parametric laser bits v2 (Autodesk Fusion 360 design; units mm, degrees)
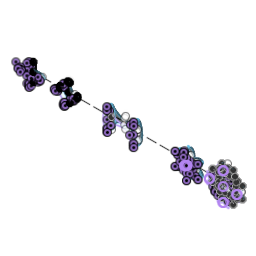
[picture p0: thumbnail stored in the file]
parameter "length" = 101.6
parameter "ch" = 6.35
parameter "width" = 25.4
parameter "sl" = 19.05
sketch "Sketch1" plane through (0, 0, 0) normal (0, 1, 0) x axis (1, 0, 0)
  line L1 (609.6, 0) -> (0, 0)
  line L2 (101.6, 50.8) -> (101.6, -50.8)
  line L3 (114.3, 50.8) -> (114.3, -50.8)
  line L4 (88.9, -50.8) -> (88.9, 50.8)
  line L5 (101.6, 50.8) -> (101.6, -50.8)
  line L6 (103.5558, -63.5) -> (99.6442, -63.5)
  line L7 (103.5558, -44.45) -> (103.5558, -63.5)
  line L8 (99.6442, -44.45) -> (103.5558, -44.45)
  line L9 (99.6442, -63.5) -> (99.6442, -44.45)
  line L10 (101.6, -44.45) -> (101.6, -63.5)
  line L11 (103.5558, 44.45) -> (103.5558, 63.5)
  line L12 (99.6442, 44.45) -> (103.5558, 44.45)
  line L13 (99.6442, 63.5) -> (99.6442, 44.45)
  line L14 (103.5558, 63.5) -> (99.6442, 63.5)
  line L15 (152.4, -12.7) -> (50.8, -12.7)
  line L16 (50.8, 12.7) -> (152.4, 12.7)
  line L17 (38.1, -0.762) -> (57.15, -0.762)
  line L18 (38.1, 0.762) -> (38.1, -0.762)
  line L19 (57.15, -0.762) -> (57.15, 0.762)
  line L20 (57.15, 0.762) -> (38.1, 0.762)
  line L21 (165.1, -0.762) -> (146.05, -0.762)
  line L22 (165.1, 0.762) -> (165.1, -0.762)
  line L23 (146.05, -0.762) -> (146.05, 0.762)
  line L24 (146.05, 0.762) -> (165.1, 0.762)
  line L25 (304.8, 50.8) -> (304.8, -50.8)
  line L26 (311.15, 50.8) -> (311.15, -50.8)
  line L27 (298.45, 50.8) -> (298.45, -50.8)
  line L28 (340.36, -6.35) -> (254, -6.35)
  curve K1 (298.45, -50.8) -> (254, -6.35)
  curve K2 (264.16, -6.35) -> (243.84, -6.35)
  curve K3 (311.15, -50.8) -> (355.6, -6.35)
  curve K4 (298.9763, -57.103) -> (297.9237, -44.497)
  curve K5 (345.44, -6.35) -> (365.76, -6.35)
  curve K6 (310.6237, -57.103) -> (311.6763, -44.497)
  line L29 (304.8, 50.8) -> (304.8, -50.8)
  curve K7 (311.15, 50.8) -> (355.6, 6.35)
  curve K8 (345.44, 6.35) -> (365.76, 6.35)
  curve K9 (310.6237, 57.103) -> (311.6763, 44.497)
  curve K10 (298.45, 50.8) -> (254, 6.35)
  curve K11 (264.16, 6.35) -> (243.84, 6.35)
  curve K12 (298.9763, 57.103) -> (297.9237, 44.497)
  line L30 (305.562, -57.15) -> (304.038, -57.15)
  line L31 (305.562, -38.1) -> (305.562, -57.15)
  line L32 (304.038, -38.1) -> (305.562, -38.1)
  line L33 (304.038, -57.15) -> (304.038, -38.1)
  line L34 (304.8, -38.1) -> (304.8, -57.15)
  line L35 (304.038, 57.15) -> (304.038, 38.1)
  line L36 (305.562, 57.15) -> (304.038, 57.15)
  line L37 (305.562, 38.1) -> (305.562, 57.15)
  line L38 (304.038, 38.1) -> (305.562, 38.1)
  line L39 (304.038, 57.15) -> (304.038, 38.1)
  line L40 (305.562, 57.15) -> (304.038, 57.15)
  line L41 (305.562, 38.1) -> (305.562, 57.15)
  line L42 (304.038, 38.1) -> (305.562, 38.1)
  line L43 (302.6737, -57.15) -> (302.6737, -38.1)
  line L44 (306.5853, -57.15) -> (302.6737, -57.15)
  line L45 (302.6737, -38.1) -> (306.5853, -38.1)
  line L46 (306.5853, -38.1) -> (306.5853, -57.15)
  line L47 (361.95, -2.3537) -> (342.9, -2.3537)
  line L48 (361.95, 1.5579) -> (361.95, -2.3537)
  line L49 (342.9, 1.5579) -> (361.95, 1.5579)
  line L50 (342.9, -2.3537) -> (342.9, 1.5579)
  line L51 (247.65, -0.762) -> (266.7, -0.762)
  line L52 (247.65, 0.762) -> (247.65, -0.762)
  line L53 (266.7, -0.762) -> (266.7, 0.762)
  line L54 (266.7, 0.762) -> (247.65, 0.762)
  line L55 (553.0223, 63.5) -> (553.0223, -63.5)
  curve K13 (553.0223, -63.5) -> (553.0223, 63.5)
  curve K14 (575.8823, 0) -> (530.1623, 0)
  line L56 (629.2223, -33.02) -> (629.2223, 0)
  curve K15 (635, 19.563) -> (710.3358, -62.0158)
  line L57 (703.58, -12.7) -> (553.0223, -12.7)
  line L58 (703.58, -12.7) -> (553.0223, -12.7)
  curve K16 (635, -44.963) -> (710.3358, 36.6158)
  line L59 (554.9781, -63.5) -> (551.0665, -63.5)
  line L60 (554.9781, -44.45) -> (554.9781, -63.5)
  line L61 (551.0665, -44.45) -> (554.9781, -44.45)
  line L62 (551.0665, -63.5) -> (551.0665, -44.45)
  line L63 (553.0223, -44.45) -> (553.0223, -63.5)
  line L64 (551.0665, 63.5) -> (551.0665, 44.45)
  line L65 (554.9781, 63.5) -> (551.0665, 63.5)
  line L66 (551.0665, 44.45) -> (554.9781, 44.45)
  line L67 (554.9781, 44.45) -> (554.9781, 63.5)
  line L68 (707.3781, -63.5) -> (707.3781, -44.45)
  line L69 (703.4665, -63.5) -> (707.3781, -63.5)
  line L70 (703.4665, -44.45) -> (703.4665, -63.5)
  line L71 (707.3781, -44.45) -> (703.4665, -44.45)
  line L72 (707.3781, 63.5) -> (707.3781, 44.45)
  line L73 (703.4665, 63.5) -> (707.3781, 63.5)
  line L74 (707.3781, 44.45) -> (703.4665, 44.45)
  line L75 (703.4665, 44.45) -> (703.4665, 63.5)
  line L76 (1224.2722, 0) -> (609.6, 0)
  line L77 (1000.4977, -75.8129) -> (996.5861, -75.8129)
  line L78 (1000.4977, -56.7629) -> (1000.4977, -75.8129)
  line L79 (996.5861, -56.7629) -> (1000.4977, -56.7629)
  line L80 (996.5861, -75.8129) -> (996.5861, -56.7629)
  line L81 (998.5419, -56.7629) -> (998.5419, -75.8129)
  line L82 (1078.2454, -38.7599) -> (1061.7476, -29.2349)
  line L83 (1079.0074, -37.4401) -> (1078.2454, -38.7599)
  line L84 (1061.7476, -29.2349) -> (1062.5096, -27.9151)
  line L85 (1062.5096, -27.9151) -> (1079.0074, -37.4401)
  line L86 (1079.0074, 37.4401) -> (1062.5096, 27.9151)
  line L87 (1078.2454, 38.7599) -> (1079.0074, 37.4401)
  line L88 (1062.5096, 27.9151) -> (1061.7476, 29.2349)
  line L89 (1061.7476, 29.2349) -> (1078.2454, 38.7599)
  line L90 (1013.3973, 76.2) -> (1013.3973, 57.15)
  line L91 (1011.8733, 76.2) -> (1013.3973, 76.2)
  line L92 (1013.3973, 57.15) -> (1011.8733, 57.15)
  line L93 (1011.8733, 57.15) -> (1011.8733, 76.2)
  line L94 (947.0251, 38.7599) -> (963.5229, 29.2349)
  line L95 (946.2631, 37.4401) -> (947.0251, 38.7599)
  line L96 (963.5229, 29.2349) -> (962.7609, 27.9151)
  line L97 (962.7609, 27.9151) -> (946.2631, 37.4401)
  line L98 (946.2631, -37.4401) -> (962.7609, -27.9151)
  line L99 (947.0251, -38.7599) -> (946.2631, -37.4401)
  line L100 (962.7609, -27.9151) -> (963.5229, -29.2349)
  line L101 (963.5229, -29.2349) -> (947.0251, -38.7599)
  line L102 (1224.2722, -101.6) -> (1224.2722, 0)
  curve K17 (1224.2722, -79.7371) -> (1201.5474, 0)
  curve K18 (1224.2722, -79.7371) -> (1246.9969, 0)
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  point P1 (0, 0)
  point P2 (0, 0)
  point P5 (101.6, 50.8)
  point P11 (101.6, 50.8)
  point P4 (101.6, -50.8)
  point P10 (101.6, -50.8)
  point P16 (101.6, -63.5)
  point P17 (101.6, -44.45)
  point P12 (99.6442, -63.5)
  point P21 (99.6442, 63.5)
  point P13 (103.5558, -63.5)
  point P18 (103.5558, 63.5)
  point P14 (103.5558, -44.45)
  point P19 (103.5558, 44.45)
  point P15 (99.6442, -44.45)
  point P20 (99.6442, 44.45)
  point P42 (254, -6.35)
  point P45 (264.16, -6.35)
  point P40 (298.45, -50.8)
  point P36 (304.8, -50.8)
  point P54 (304.8, -50.8)
  point P37 (304.8, 50.8)
  point P55 (304.8, 50.8)
  point P47 (311.15, -50.8)
  point P46 (355.6, -6.35)
  point P44 (243.84, -6.35)
  point P50 (365.76, -6.35)
  point P51 (345.44, -6.35)
  point P48 (297.9237, -44.497)
  point P52 (311.6763, -44.497)
  point P49 (298.9763, -57.103)
  point P53 (310.6237, -57.103)
  point P63 (298.45, 50.8)
  point P62 (254, 6.35)
  point P64 (243.84, 6.35)
  point P65 (264.16, 6.35)
  point P56 (355.6, 6.35)
  point P57 (311.15, 50.8)
  point P66 (297.9237, 44.497)
  point P67 (298.9763, 57.103)
  point P58 (365.76, 6.35)
  point P59 (345.44, 6.35)
  point P60 (311.6763, 44.497)
  point P61 (310.6237, 57.103)
  point P76 (304.8, -57.15)
  point P77 (304.8, -38.1)
  point P72 (304.038, -57.15)
  point P79 (304.038, 57.15)
  point P73 (305.562, -57.15)
  point P80 (305.562, 57.15)
  point P74 (305.562, -38.1)
  point P81 (305.562, 38.1)
  point P75 (304.038, -38.1)
  point P78 (304.038, 38.1)
  point P100 (553.0223, 0)
  point P98 (553.0223, -63.5)
  point P102 (553.0223, -63.5)
  point P110 (553.0223, -12.7)
  point P114 (553.0223, 38.1)
  point P108 (710.3358, -62.0158)
  point P115 (710.3358, 36.6158)
  point P109 (635, 19.563)
  point P116 (635, -44.963)
  point P112 (553.0223, -12.7)
  point P111 (703.58, -12.7)
  point P113 (703.58, -12.7)
  point P121 (553.0223, -63.5)
  point P122 (553.0223, -44.45)
  point P117 (551.0665, -63.5)
  point P124 (551.0665, 63.5)
  point P118 (554.9781, -63.5)
  point P125 (554.9781, 63.5)
  point P119 (554.9781, -44.45)
  point P126 (554.9781, 44.45)
  point P120 (551.0665, -44.45)
  point P123 (551.0665, 44.45)
  point P128 (707.3781, -63.5)
  point P129 (703.4665, -63.5)
  point P130 (703.4665, -44.45)
  point P127 (707.3781, -44.45)
  point P131 (707.3781, 44.45)
  point P132 (707.3781, 63.5)
  point P133 (703.4665, 63.5)
  point P134 (703.4665, 44.45)
  point P142 (998.5419, -75.8129)
  point P143 (998.5419, -56.7629)
  point P170 (1201.5474, 0)
  point P175 (1224.2722, -79.7371)
  point P176 (1246.9969, 0)
  point P171 (1175.7919, -12.7079)
  point P177 (1272.7525, -12.7079)
  point P172 (1165.6087, -43.2072)
  point P178 (1282.9356, -43.2072)
  point P173 (1191.0634, -50.8314)
  point P179 (1257.481, -50.8314)
  point P174 (1191.0621, -86.4135)
  point P180 (1257.4822, -86.4135)
  point P181 (1224.2722, -79.7371)
  point P182 (1210.0943, -3.4854)
  point P186 (1238.45, -3.4854)
  point P183 (1193.0006, 3.4854)
  point P187 (1255.5438, 3.4854)
  point P184 (1197.4512, -97.9793)
  point P188 (1251.0931, -97.9793)
  point P185 (1251.0931, -61.4949)
  point P189 (1197.4512, -61.4949)
  point P135 (1224.2722, 0)
  point P272 (1224.2722, 0)
  point P275 (1050.3587, 0)
  point P283 (101.6, 0)
  point P296 (304.8, 0)
  point P3 (609.6, 0)
  point P22 (165.1, -0.762)
  point P30 (146.05, -0.762)
  point P82 (302.6737, -57.15)
  point P83 (306.5853, -57.15)
  point P86 (302.6737, -38.1)
  point P90 (361.95, -2.3537)
  point P91 (361.95, 1.5579)
  point P94 (342.9, -2.3537)
  point P99 (553.0223, 63.5)
  point P138 (996.5861, -75.8129)
  point P139 (1000.4977, -75.8129)
  point P141 (996.5861, -56.7629)
  point P226 (1222.3164, -80.3091)
  point P227 (1226.228, -80.3091)
  point P229 (1222.3164, -61.2591)
  coincident P1 P2
  horizontal L1
  vertical L2
  parallel L3 L4
  coincident P5 P11
  parallel L2 L5
  coincident P4 P10
  horizontal L6
  vertical L7
  horizontal L8
  vertical L9
  midpoint L6 P16
  midpoint L8 P17
  collinear L5 L10
  symmetric L1 P12 P21
  symmetric L1 P13 P18
  symmetric L1 P14 P19
  symmetric L1 P15 P20
  parallel L15 L16
  vertical L25
  midpoint L1 L25
  parallel L1 L28
  midpoint P42 K2
  coincident L28 P45
  midpoint P40 K4
  symmetric P36 L25 P54
  symmetric P37 L25 P55
  symmetric L25 P40 P47
  symmetric L25 P42 P46
  symmetric L25 P44 P50
  symmetric L25 P45 P51
  symmetric L25 P48 P52
  symmetric L25 P49 P53
  symmetric L1 P40 P63
  symmetric L1 P42 P62
  symmetric L1 P44 P64
  symmetric L1 P45 P65
  symmetric L1 P46 P56
  symmetric L1 P47 P57
  symmetric L1 P48 P66
  symmetric L1 P49 P67
  symmetric L1 P50 P58
  symmetric L1 P51 P59
  symmetric L1 P52 P60
  symmetric L1 P53 P61
  horizontal L30
  vertical L31
  horizontal L32
  vertical L33
  midpoint L30 P76
  midpoint L32 P77
  collinear L25 L34
  symmetric L1 P72 P79
  symmetric L1 P73 P80
  symmetric L1 P74 P81
  symmetric L1 P75 P78
  horizontal L44
  vertical L46
  horizontal L45
  vertical L43
  vertical L55
  midpoint L55 P100
  coincident P98 P102
  vertical L56
  coincident L55 P110
  perpendicular K13 L57
  symmetric P98 L57 P114
  symmetric P108 L57 P115
  symmetric P109 L57 P116
  symmetric K15 L57 K16
  symmetric P110 L57 P112
  symmetric P111 L57 P113
  horizontal L59
  vertical L60
  horizontal L61
  vertical L62
  midpoint L59 P121
  midpoint L61 P122
  collinear K13 L63
  symmetric L1 P117 P124
  symmetric L1 P118 P125
  symmetric L1 P119 P126
  symmetric L1 P120 P123
  symmetric L56 P117 P128
  symmetric L56 P118 P129
  symmetric L56 P119 P130
  symmetric L56 P120 P127
  symmetric L56 P123 P131
  symmetric L56 P124 P132
  symmetric L56 P125 P133
  symmetric L56 P126 P134
  horizontal L76
  collinear L1 L76
  horizontal L77
  vertical L78
  horizontal L79
  vertical L80
  midpoint L77 P142
  midpoint L79 P143
  perpendicular L76 L102
  coincident L76 P170
  coincident L102 P175
  symmetric L102 P170 P176
  symmetric L102 P171 P177
  symmetric L102 P172 P178
  symmetric L102 P173 P179
  symmetric L102 P174 P180
  symmetric L102 P175 P181
  symmetric L102 P182 P186
  symmetric L102 P183 P187
  symmetric L102 P184 P188
  symmetric L102 P185 P189
  coincident P135 P272
  coincident L76 P275
  midpoint L2 P283
  midpoint L1 P296
  dimension "d4" distance P2 P3 = 609.6
  dimension "d5" distance P4 P5 = 101.6 (= "length")
  dimension "d6" distance L1 P4 = 50.8
  dimension "d8" diameter = 25.4 (= "width")
  dimension "d11" distance P12 P15 = 19.05 (= "sl")
  dimension "d12" distance P1 L2 = 101.6 (= "length")
  dimension "d13" diameter = 25.4 (= "width")
  dimension "d14" = 3.9116 (= "Linear Dimension-8")
  dimension "d15" distance P22 P30 = 19.05 (= "sl")
  dimension "d16" distance P36 P37 = 101.6 (= "length")
  dimension "d17" = 6.35
  dimension "d18" = -6.35
  dimension "d19" distance L1 L28 = 6.35
  dimension "d20" distance L25 P42 = 50.8 (= "length / 2")
  dimension "d22" distance P72 P75 = 19.05 (= "sl")
  dimension "d23" distance P82 P83 = 3.9116 (= "Linear Dimension-17")
  dimension "d24" distance P82 P86 = 19.05 (= "sl")
  dimension "d25" distance P90 P91 = 3.9116 (= "Linear Dimension-19")
  dimension "d26" distance P90 P94 = 19.05 (= "sl")
  dimension "d27" distance P98 P99 = 127
  dimension "d28" distance L1 P98 = 63.5
  dimension "d29" distance K13 L56 = 76.2
  dimension "d33" distance P98 L57 = 50.8
  dimension "d34" distance P117 P118 = 3.9116 (= "Linear Dimension-25")
  dimension "d35" distance P117 P120 = 19.05 (= "sl")
  dimension "d39" = 38.1
  dimension "d41" distance P138 P139 = 3.9116 (= "Linear Dimension-29")
  dimension "d42" distance P138 P141 = 19.05 (= "sl")
  dimension "d50" distance P226 P227 = 3.9116 (= "Linear Dimension-31")
  dimension "d51" distance P226 P229 = 19.05 (= "sl")
  dimension "d56" diameter = 6.35
  dimension "d70" distance L7 L9 = 3.9116 (= "Linear Dimension-30")
  dimension "d71" distance L39 L41 = 1.524
  dimension "d49" C-Pattern2-Angle = 360
  dimension "d53" C-Pattern3-Angle = 360
  dimension "d55" C-Pattern4-Angle = 360
  dimension "d73" C-Pattern4-Angle = 360
  dimension "d75" C-Pattern5-Angle = 360
extrude "Extrude1" new body sketch "Sketch1" no distance stored
extrude "Extrude2" new body sketch "Sketch1" no distance stored
extrude "Extrude3" new body sketch "Sketch1" no distance stored
extrude "Extrude4" new body sketch "Sketch1" no distance stored
extrude "Extrude6" new body sketch "Sketch1" no distance stored
work_plane "WorkPlane1" AlongDistance 25.4
sketch "Parts for laser" plane through (0, -25.4, 0) normal (0, -1, 0) x axis (-1, 0, 0)
  line L1 (-146.05, -1.9558) -> (-146.05, 1.9558)
  line L2 (-114.3, -12.7) -> (-152.4, -12.7)
  line L3 (-114.3, -50.8) -> (-114.3, -12.7)
  line L4 (-103.5558, -44.45) -> (-103.5558, -63.3485)
  line L5 (-99.6442, -44.45) -> (-103.5558, -44.45)
  line L6 (-99.6442, -63.3485) -> (-99.6442, -44.45)
  line L7 (-88.9, -12.7) -> (-88.9, -50.8)
  line L8 (-50.8, -12.7) -> (-88.9, -12.7)
  line L9 (-57.15, 1.9558) -> (-57.15, -1.9558)
  line L10 (-88.9, 12.7) -> (-50.8, 12.7)
  line L11 (-88.9, 50.8) -> (-88.9, 12.7)
  line L12 (-99.6442, 44.45) -> (-99.6442, 63.3485)
  line L13 (-103.5558, 44.45) -> (-99.6442, 44.45)
  line L14 (-103.5558, 63.3485) -> (-103.5558, 44.45)
  line L15 (-114.3, 12.7) -> (-114.3, 50.8)
  line L16 (-152.4, 12.7) -> (-114.3, 12.7)
  line L17 (-342.9, 1.5579) -> (-361.7559, 1.5579)
  line L18 (-342.9, -2.3537) -> (-342.9, 1.5579)
  line L19 (-361.4977, -2.3537) -> (-342.9, -2.3537)
  curve K1 (-311.15, -50.8) -> (-355.6, -6.35)
  line L20 (-306.5853, -38.1) -> (-306.5853, -56.8939)
  line L21 (-302.6737, -38.1) -> (-306.5853, -38.1)
  line L22 (-302.6737, -56.7834) -> (-302.6737, -38.1)
  curve K2 (-298.45, -50.8) -> (-254, -6.35)
  line L23 (-266.7, -0.762) -> (-247.6959, -0.762)
  line L24 (-266.7, 0.762) -> (-266.7, -0.762)
  line L25 (-247.6959, 0.762) -> (-266.7, 0.762)
  curve K3 (-298.45, 50.8) -> (-254, 6.35)
  line L26 (-306.9263, 38.1) -> (-303.0147, 38.1)
  curve K4 (-311.15, 50.8) -> (-355.6, 6.35)
  line L27 (-703.4665, -63.2672) -> (-703.4665, -44.45)
  curve K5 (-688.1797, -41.6919) -> (-566.8067, -50.657)
  line L28 (-554.9781, -44.45) -> (-554.9781, -63.2672)
  line L29 (-551.0665, -44.45) -> (-554.9781, -44.45)
  line L30 (-551.0665, -63.2672) -> (-551.0665, -44.45)
  line L31 (-551.0665, 44.45) -> (-551.0665, 63.2672)
  line L32 (-554.9781, 44.45) -> (-551.0665, 44.45)
  line L33 (-554.9781, 63.2672) -> (-554.9781, 44.45)
  curve K6 (-683.0164, 12.5931) -> (-574.8566, 18.8078)
  line L34 (-703.4665, 44.45) -> (-703.4665, 63.2672)
  line L35 (-707.3781, 44.45) -> (-703.4665, 44.45)
  line L36 (-707.3781, 63.2672) -> (-707.3781, 44.45)
  line L37 (-707.3781, -44.45) -> (-707.3781, -63.2672)
  line L38 (-703.4665, -44.45) -> (-707.3781, -44.45)
  line L39 (-962.7609, 27.9151) -> (-946.2872, 37.4262)
  line L40 (-963.5229, 29.2349) -> (-962.7609, 27.9151)
  line L41 (-947.0483, 38.7465) -> (-963.5229, 29.2349)
  line L42 (-1061.7476, 29.2349) -> (-1078.2209, 38.7458)
  line L43 (-1062.5096, 27.9151) -> (-1061.7476, 29.2349)
  line L44 (-1078.9836, 37.4263) -> (-1062.5096, 27.9151)
  line L45 (-1062.5096, -27.9151) -> (-1078.9806, -37.4246)
  line L46 (-1061.7476, -29.2349) -> (-1062.5096, -27.9151)
  line L47 (-1078.2203, -38.7454) -> (-1061.7476, -29.2349)
  line L48 (-1000.4977, -56.7629) -> (-1000.4977, -67.2117)
  line L49 (-996.5861, -56.7629) -> (-1000.4977, -56.7629)
  line L50 (-996.5861, -58.4354) -> (-996.5861, -56.7629)
  line L51 (-963.5229, -29.2349) -> (-947.2229, -38.6457)
  line L52 (-962.7609, -27.9151) -> (-963.5229, -29.2349)
  line L53 (-946.3992, -37.3615) -> (-962.7609, -27.9151)
  curve K7 (-1224.2722, -79.7371) -> (-1194.345, -59.4676)
  curve K8 (-1178.0758, -48.9623) -> (-1194.345, -59.4676)
  line L54 (-1182.3384, -44.6997) -> (-1178.0758, -48.9623)
  line L55 (-1179.5725, -41.9338) -> (-1182.3384, -44.6997)
  line L56 (-1175.3095, -46.1967) -> (-1179.5725, -41.9338)
  curve K9 (-1175.3095, -46.1967) -> (-1164.7877, -29.9211)
  curve K10 (-1144.5351, 0) -> (-1164.7877, -29.9211)
  curve K11 (-1144.5351, 0) -> (-1164.8066, 29.9221)
  curve K12 (-1175.3099, 46.1964) -> (-1164.8066, 29.9221)
  line L57 (-1179.5725, 41.9338) -> (-1175.3099, 46.1964)
  line L58 (-1182.3384, 44.6997) -> (-1179.5725, 41.9338)
  line L59 (-1178.0758, 48.9623) -> (-1182.3384, 44.6997)
  curve K13 (-1178.0758, 48.9623) -> (-1194.3501, 59.4656)
  curve K14 (-1224.2722, 79.7371) -> (-1194.3501, 59.4656)
  curve K15 (-1224.2722, 79.7371) -> (-1254.1942, 59.4656)
  curve K16 (-1270.4686, 48.9623) -> (-1254.1942, 59.4656)
  line L60 (-1266.206, 44.6997) -> (-1270.4686, 48.9623)
  line L61 (-1268.9719, 41.9338) -> (-1266.206, 44.6997)
  line L62 (-1273.2345, 46.1964) -> (-1268.9719, 41.9338)
  curve K17 (-1273.2345, 46.1964) -> (-1283.7377, 29.9221)
  curve K18 (-1304.0093, 0) -> (-1283.7377, 29.9221)
  curve K19 (-1304.0093, 0) -> (-1283.7567, -29.9211)
  curve K20 (-1273.2348, -46.1967) -> (-1283.7567, -29.9211)
  line L63 (-1268.9719, -41.9338) -> (-1273.2348, -46.1967)
  line L64 (-1266.206, -44.6997) -> (-1268.9719, -41.9338)
  line L65 (-1270.4686, -48.9623) -> (-1266.206, -44.6997)
  curve K21 (-1270.4686, -48.9623) -> (-1254.1994, -59.4676)
  curve K22 (-1224.2722, -79.7371) -> (-1254.1994, -59.4676)
  line L66 (-1012.6657, 76.2) -> (-1012.6067, 76.2)
  line L67 (-57.15, -1.9558) -> (-38.2515, -1.9558)
  line L68 (-38.2515, 1.9558) -> (-57.15, 1.9558)
  line L69 (-146.05, 1.9558) -> (-164.9485, 1.9558)
  line L70 (-164.9485, -1.9558) -> (-146.05, -1.9558)
  line L71 (-303.0147, 38.1) -> (-303.0147, 56.8939)
  line L72 (-306.9263, 56.7834) -> (-306.9263, 38.1)
  arc A1 centre (-152.4, 0) radius 12.7 clockwise from (-164.9485, 1.9558) to (-152.4, 12.7)
  arc A2 centre (-152.4, 0) radius 12.7 clockwise from (-152.4, -12.7) to (-164.9485, -1.9558)
  arc A3 centre (-101.6, -50.8) radius 12.7 clockwise from (-103.5558, -63.3485) to (-114.3, -50.8)
  arc A4 centre (-101.6, -50.8) radius 12.7 clockwise from (-88.9, -50.8) to (-99.6442, -63.3485)
  arc A5 centre (-50.8, 0) radius 12.7 clockwise from (-38.2515, -1.9558) to (-50.8, -12.7)
  arc A6 centre (-50.8, 0) radius 12.7 clockwise from (-50.8, 12.7) to (-38.2515, 1.9558)
  arc A7 centre (-101.6, 50.8) radius 12.7 clockwise from (-99.6442, 63.3485) to (-88.9, 50.8)
  arc A8 centre (-101.6, 50.8) radius 12.7 clockwise from (-114.3, 50.8) to (-103.5558, 63.3485)
  arc A9 centre (-355.6, 0) radius 6.35 clockwise from (-361.7559, 1.5579) to (-355.6, 6.35)
  arc A10 centre (-355.6, 0) radius 6.35 clockwise from (-355.6, -6.35) to (-361.4977, -2.3537)
  arc A11 centre (-304.8, -50.8) radius 6.35 clockwise from (-306.5853, -56.8939) to (-311.15, -50.8)
  arc A12 centre (-304.8, -50.8) radius 6.35 clockwise from (-298.45, -50.8) to (-302.6737, -56.7834)
  arc A13 centre (-254, 0) radius 6.35 clockwise from (-247.6959, -0.762) to (-254, -6.35)
  arc A14 centre (-254, 0) radius 6.35 clockwise from (-254, 6.35) to (-247.6959, 0.762)
  arc A15 centre (-304.8, 50.8) radius 6.35 clockwise from (-303.0147, 56.8939) to (-298.45, 50.8)
  arc A16 centre (-304.8, 50.8) radius 6.35 clockwise from (-311.15, 50.8) to (-306.9263, 56.7834)
  closed curve K23 centre (-705.4223, 0)
  closed curve K24 centre (-553.0223, 0)
  closed curve K25 centre (-553.0223, 0)
  closed curve K26 centre (-553.0223, 0)
  closed curve K27 centre (-705.4223, 0)
  closed curve K28 centre (-705.4223, 0)
  closed curve K29 centre (-979.5465, -18.577)
  closed curve K30 centre (-979.6408, 19.0565)
  closed curve K31 centre (-979.6408, 19.0565)
  closed curve K32 centre (-1012.6362, 38.1)
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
